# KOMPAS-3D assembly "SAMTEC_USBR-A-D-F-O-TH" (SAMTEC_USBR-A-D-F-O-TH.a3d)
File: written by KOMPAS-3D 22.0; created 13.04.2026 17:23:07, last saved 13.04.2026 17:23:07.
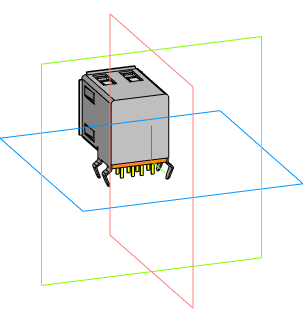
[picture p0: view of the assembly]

Document properties: Автор: Andrey; Полное имя файла: C:\Users\User1\Documents\SAMTEC_USBR-A-D-F-O-TH.a3d

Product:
- Component [assembly]: USBR-A-D-F-O-TH  | qty 1  | source file: USBR-A-D-F-O-TH.a3d
- Part/product: SAMTEC_USBR-A-D-F-O-TH
    Комментарий: SAMTEC_USBR-A-D-F-O-TH

Referenced files in C:\Users\User1\Documents\: USBR-A-D-F-O-TH.a3d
